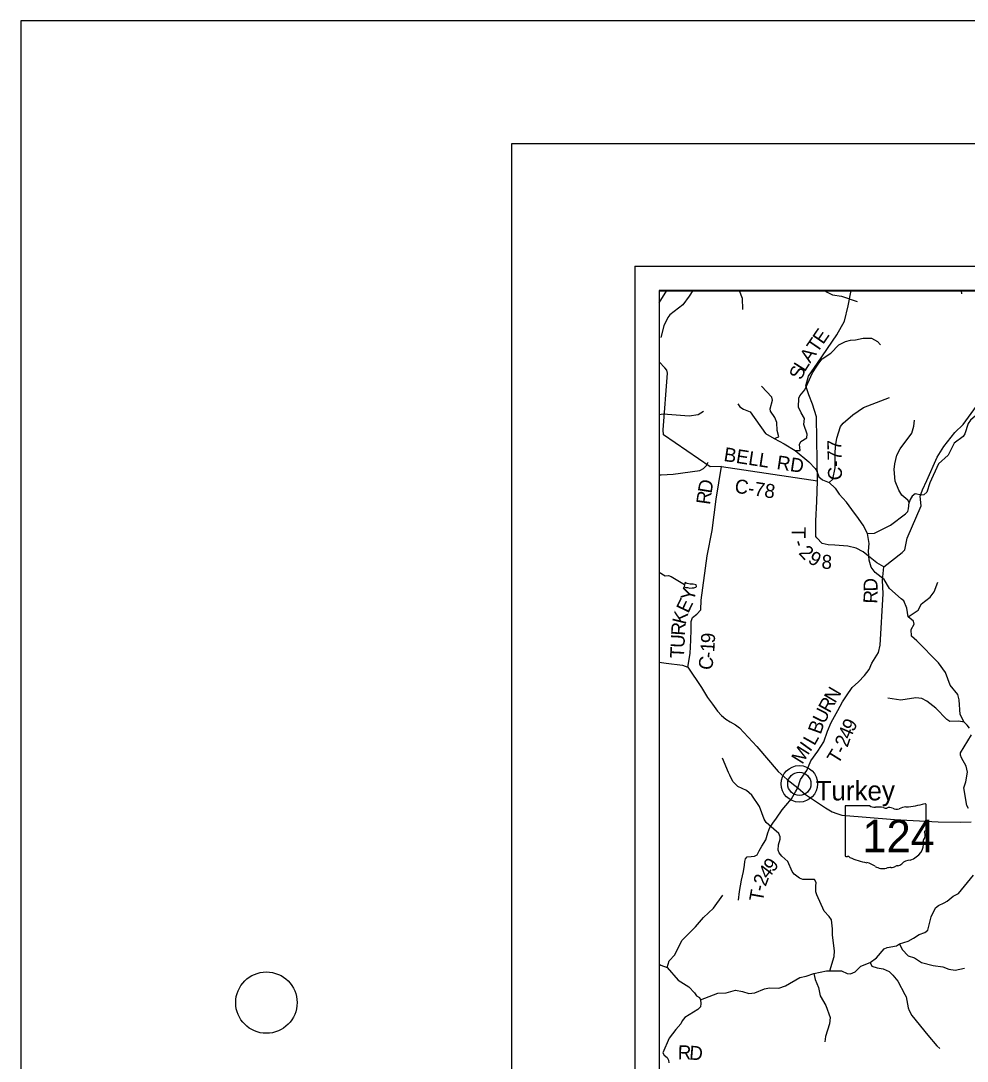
# Model space of a CAD drawing. Extents: x 0 to 34, y 0 to 22.
# Drawn here: x 0 to 3.854, y 17.761 to 22 of the extents above; entities that cross this region are included whole.
import ezdxf

# ---------------------------------------------------------------- set-up
doc = ezdxf.new("R2010")
doc.units = 0
for name, color, linetype in [('GM_X_County', 7, 'Continuous'), ('GM_X_County_Road', 7, 'Continuous'), ('GM_X_County_Road_Text', 7, 'Continuous'), ('GM_X_Minor_Lake', 7, 'Continuous'), ('GM_X_Minor_River', 7, 'Continuous'), ('GM_X_State_Location', 7, 'Continuous'), ('GM_X_State_Route', 7, 'Continuous'), ('GM_X_State_Shield', 7, 'Continuous'), ('GM_X_Township', 7, 'Continuous'), ('GM_X_Township_Road', 7, 'Continuous'), ('GM_X_Township_Road_Text', 7, 'Continuous'), ('GM_X_Unincorporated', 7, 'Continuous'), ('GM_X_Unincorporated_Location', 7, 'Continuous'), ('GM_X_Unincorporated_Text', 7, 'Continuous'), ('SH_Border', 7, 'Continuous'), ('SH_Cut_Line', 7, 'Continuous'), ('SH_Data', 7, 'Continuous')]:
    doc.layers.add(name, color=color, linetype=linetype)

msp = doc.modelspace()

# ---------------------------------------------------------------- linework, layer by layer
at = {"layer": 'GM_X_County'}
msp.add_lwpolyline([(7.6111, 20.9006), (2.6, 20.9006), (2.6, 14.46)], dxfattribs=at)
at = {"layer": 'GM_X_County_Road'}
for points in [[(3.2448, 20.1261), (3.2409, 20.2936), (3.2401, 20.3871), (3.2231, 20.4376), (3.2085, 20.4756), (3.1968, 20.5135), (3.2073, 20.552), (3.2446, 20.6047), (3.3224, 20.7203), (3.3537, 20.7766), (3.3689, 20.8386), (3.3814, 20.9006)], [(2.716, 19.367), (2.7257, 19.423), (2.7284, 19.4769), (2.7293, 19.5198), (2.7294, 19.5521), (2.7358, 19.5696), (2.7528, 19.583), (2.7686, 19.6009), (2.7698, 19.6396), (2.7948, 19.8201), (2.8154, 19.9231), (2.8313, 20.0515), (2.8536, 20.1849), (2.8065, 20.1823), (2.6165, 20.3129), (2.6151, 20.3339), (2.6337, 20.5651), (2.6302, 20.5763), (2.6226, 20.5864), (2.6, 20.611)], [(2.8536, 20.1849), (3.2448, 20.1261)]]:
    msp.add_lwpolyline(points, dxfattribs=at)
at = {"layer": 'GM_X_Minor_Lake'}
for points in [[(2.7029, 19.704), (2.701, 19.6942), (2.7074, 19.6918), (2.7145, 19.6906), (2.724, 19.689), (2.7338, 19.6893), (2.7406, 19.69), (2.7482, 19.6926), (2.7517, 19.696), (2.7498, 19.7017), (2.7381, 19.7044), (2.7257, 19.7049), (2.7136, 19.7077), (2.709, 19.7089), (2.7053, 19.7116)], [(2.7053, 19.7116), (2.7029, 19.704)]]:
    msp.add_lwpolyline(points, dxfattribs=at)
at = {"layer": 'GM_X_Minor_River'}
for points in [[(2.7361, 20.9006), (2.7216, 20.878), (2.6951, 20.8431), (2.6435, 20.8015), (2.6349, 20.7918), (2.6187, 20.7567), (2.606, 20.7095)], [(2.9249, 20.9006), (2.9371, 20.8699), (2.9382, 20.8243)], [(3.2744, 20.9006), (3.2831, 20.8945), (3.3057, 20.8831), (3.3413, 20.8779), (3.405, 20.8558)], [(3.8296, 20.9006), (3.8296, 20.8999), (3.8305, 20.8881)], [(4.0014, 20.7517), (3.9944, 20.7211), (3.9907, 20.6847), (3.9892, 20.5855), (3.9875, 20.5343), (3.9806, 20.5123), (3.9499, 20.4529), (3.9157, 20.4151), (3.8675, 20.373), (3.8581, 20.3595), (3.844, 20.3168), (3.837, 20.3071), (3.8004, 20.2789), (3.7897, 20.257), (3.7756, 20.2307), (3.7366, 20.1957), (3.7009, 20.118), (3.6888, 20.0795), (3.6776, 20.0694), (3.6677, 20.0677), (3.6413, 20.0735), (3.6293, 20.0631), (3.6211, 20.0503), (3.617, 20.0375)], [(3.1529, 20.249), (3.1741, 20.2494), (3.1708, 20.2742), (3.176, 20.2862), (3.2006, 20.3014), (3.202, 20.3154), (3.1887, 20.3555), (3.191, 20.3802), (3.1774, 20.4032), (3.1668, 20.4266), (3.1675, 20.4623), (3.1719, 20.4721), (3.1928, 20.4964), (3.2242, 20.5665), (3.2382, 20.5887), (3.2464, 20.6011), (3.2632, 20.6232), (3.2978, 20.6458), (3.3307, 20.6794), (3.3575, 20.6933), (3.3789, 20.6994), (3.3991, 20.7006), (3.4295, 20.7065), (3.4641, 20.7074), (3.4889, 20.6929), (3.5004, 20.6797)], [(3.0672, 20.2988), (3.0864, 20.3057), (3.08, 20.3313), (3.0783, 20.3632), (3.0707, 20.3842), (3.0534, 20.4096), (3.052, 20.4191), (3.0607, 20.454), (3.0579, 20.4673), (3.0158, 20.511)], [(2.9192, 20.4402), (2.9284, 20.4271), (2.9423, 20.4177), (2.9698, 20.4073), (3.0323, 20.3181), (3.0672, 20.2988), (3.1086, 20.2768), (3.1529, 20.249), (3.2094, 20.2036), (3.2346, 20.1758), (3.2413, 20.1646), (3.2496, 20.1424), (3.2641, 20.1293), (3.292, 20.1189), (3.3167, 20.096), (3.3325, 20.0718), (3.3616, 20.0394)], [(3.292, 20.1189), (3.306, 20.1331), (3.3167, 20.1788), (3.3164, 20.2442), (3.3193, 20.2742), (3.3232, 20.2996), (3.3374, 20.3475), (3.3483, 20.3614), (3.388, 20.3953), (3.4311, 20.4241), (3.537, 20.4648)], [(2.6, 20.3958), (2.6158, 20.3989), (2.7219, 20.3913), (2.7577, 20.3963), (2.7804, 20.41)], [(3.617, 20.0375), (3.6115, 20.0471), (3.5876, 20.0672), (3.5747, 20.0872), (3.5602, 20.1243), (3.5565, 20.1715), (3.5593, 20.1954), (3.5675, 20.2298), (3.5813, 20.2558), (3.6284, 20.3196), (3.6366, 20.3487), (3.6385, 20.3733)], [(2.6, 20.1502), (2.6077, 20.1505), (2.6563, 20.1527), (2.7656, 20.1682), (2.7798, 20.1763), (2.7925, 20.1886), (2.7989, 20.2014)], [(3.8631, 19.1187), (3.8534, 19.1302), (3.8407, 19.1421), (3.8247, 19.1744), (3.8208, 19.234), (3.8153, 19.256), (3.7847, 19.2931), (3.7651, 19.3445), (3.7371, 19.3838), (3.6488, 19.4737), (3.627, 19.4929), (3.6258, 19.5198), (3.6381, 19.5421), (3.6356, 19.5546), (3.6127, 19.5723), (3.6081, 19.6068), (3.5955, 19.6365), (3.5846, 19.6457), (3.537, 19.6867), (3.5154, 19.7245), (3.4783, 19.7525), (3.4626, 19.7746), (3.4542, 19.802), (3.4519, 19.8396), (3.4552, 19.871), (3.4481, 19.9116), (3.4302, 19.9448), (3.4041, 19.9818), (3.3948, 19.9937), (3.3616, 20.0394)], [(3.4481, 19.9116), (3.4761, 19.9129), (3.5418, 19.9456), (3.6025, 19.992), (3.612, 20.001), (3.6148, 20.0112), (3.617, 20.0375)], [(2.6, 19.7541), (2.6242, 19.7393), (2.6375, 19.7407), (2.6488, 19.736), (2.7029, 19.704)], [(3.6127, 19.5723), (3.6538, 19.5992), (3.6673, 19.6252), (3.7035, 19.6521), (3.7188, 19.6743), (3.7347, 19.7128)], [(3.8407, 19.1421), (3.8203, 19.1464), (3.7832, 19.1457), (3.7708, 19.1534), (3.7259, 19.1997), (3.6887, 19.2285), (3.6684, 19.2393), (3.6446, 19.2414), (3.5836, 19.2325), (3.5307, 19.2402)], [(3.8584, 18.7905), (3.8521, 18.8027), (3.8395, 18.8745), (3.8485, 18.9001), (3.8553, 18.9391), (3.8495, 18.9634), (3.8302, 18.9977), (3.8265, 19.0076), (3.827, 19.0179), (3.8712, 19.0906)], [(3.2949, 18.13), (3.3125, 18.1878), (3.3131, 18.2109), (3.3051, 18.2751), (3.3049, 18.3012), (3.3008, 18.338), (3.2918, 18.351), (3.2708, 18.3728), (3.2409, 18.4391), (3.2368, 18.452), (3.2371, 18.4747), (3.2387, 18.4891), (3.2324, 18.5021), (3.184, 18.5018), (3.1715, 18.5072), (3.1486, 18.5238), (3.1408, 18.5341), (3.1238, 18.5744), (3.0994, 18.597), (3.0882, 18.61), (3.0834, 18.6211), (3.0851, 18.643), (3.0918, 18.6661), (3.0919, 18.6756), (3.0863, 18.6889), (3.0357, 18.7345), (3.0264, 18.7475), (3.0168, 18.773), (3.0076, 18.7984), (2.977, 18.8457), (2.9545, 18.8642), (2.9199, 18.8804), (2.9, 18.9011), (2.8874, 18.9262), (2.8818, 18.9373), (2.8571, 18.9959)], [(2.7671, 18.0108), (2.8381, 18.0386), (2.8729, 18.0405), (2.9105, 18.0504), (2.9381, 18.0452), (2.9641, 18.0366), (2.9887, 18.0397), (3.0286, 18.0568), (3.0491, 18.06), (3.0869, 18.0596), (3.1142, 18.0688), (3.1728, 18.1028), (3.1975, 18.1074), (3.2294, 18.1189), (3.2805, 18.129), (3.2949, 18.13), (3.3418, 18.1295), (3.3644, 18.1187), (3.378, 18.1174), (3.3978, 18.1252), (3.4203, 18.1489), (3.4587, 18.1633), (3.485, 18.1831), (3.5152, 18.2192), (3.5274, 18.224), (3.5653, 18.2308), (3.5779, 18.2402), (3.6128, 18.2504), (3.6352, 18.262), (3.6577, 18.2777), (3.6816, 18.2854), (3.6934, 18.2959), (3.7072, 18.3492), (3.7246, 18.3858), (3.7364, 18.3963), (3.7596, 18.4071), (3.7721, 18.413), (3.7966, 18.4344), (3.8186, 18.4448), (3.8788, 18.5196)], [(2.6322, 18.1433), (2.6396, 18.1698), (2.6637, 18.1942), (2.6923, 18.2527), (2.7473, 18.3086), (2.7803, 18.3462), (2.8204, 18.3844), (2.8583, 18.4375)], [(3.5779, 18.2402), (3.589, 18.2162), (3.6137, 18.1905), (3.6397, 18.1827), (3.6671, 18.1631), (3.7151, 18.1509), (3.7547, 18.146), (3.7796, 18.137), (3.8045, 18.1322), (3.8425, 18.1398)], [(2.6, 18.157), (2.6066, 18.153)], [(2.6066, 18.153), (2.6322, 18.1433), (2.6771, 18.0917), (2.7203, 18.064), (2.7439, 18.0403), (2.7517, 18.0277), (2.7638, 18.0211), (2.7671, 18.0108), (2.7696, 17.996), (2.7679, 17.9824), (2.7572, 17.9715), (2.704, 17.9398), (2.6936, 17.9263), (2.6882, 17.9131), (2.6668, 17.8905), (2.6399, 17.8548), (2.614, 17.7959), (2.62, 17.7864), (2.6323, 17.7764), (2.6379, 17.7657), (2.6386, 17.7547)], [(3.4587, 18.1633), (3.4653, 18.148), (3.4876, 18.1414), (3.5122, 18.1381), (3.5359, 18.1265), (3.5512, 18.1123), (3.5707, 18.0875), (3.5996, 18.033), (3.6052, 18.0231), (3.6139, 17.9787), (3.6168, 17.9673), (3.6276, 17.9482), (3.6937, 17.8679), (3.73, 17.824), (3.7427, 17.8136)], [(3.2294, 18.1189), (3.2352, 18.0942), (3.2488, 18.0622), (3.2549, 18.0273), (3.278, 17.9888), (3.2953, 17.9397), (3.2935, 17.9143), (3.2767, 17.8614), (3.2735, 17.8402)]]:
    msp.add_lwpolyline(points, dxfattribs=at)
at = {"layer": 'GM_X_State_Route'}
msp.add_lwpolyline([(2.6, 19.3872), (2.6279, 19.3834), (2.6938, 19.3742), (2.716, 19.367), (2.7722, 19.2838), (2.796, 19.2436), (2.8161, 19.2153), (2.837, 19.1877), (2.8531, 19.1693), (2.8703, 19.1546), (2.8884, 19.1445), (2.9099, 19.1321), (2.9264, 19.1201), (2.9975, 19.0437), (3.0838, 18.9416), (3.1206, 18.9089), (3.1642, 18.8754), (3.1957, 18.8484), (3.2769, 18.7939), (3.304, 18.7776), (3.3232, 18.7702), (3.3436, 18.7642), (3.5575, 18.7465), (3.7355, 18.7371), (3.8268, 18.7356), (3.8692, 18.7363)], dxfattribs=at)
at = {"layer": 'GM_X_State_Shield'}
for p, q in [((3.3564, 18.799), (3.3564, 18.5989)), ((3.4562, 18.8024), (3.3597, 18.8024)), ((3.686, 18.7027), (3.686, 18.8074)), ((3.686, 18.7027), (3.686, 18.7027))]:
    msp.add_line(p, q, dxfattribs=at)
for centre, major_axis, start_param, end_param in [((3.3602, 18.7994), (0.00382, 0), 1.712693, 3.28349), ((3.4792, 18.8257), (0.037, 0), 4.042523, 4.731795), ((3.4915, 18.6901), (0.133, 0), 1.404758, 1.657858), ((3.5216, 18.8005), (0.0107, 0), 3.836095, 5.185415), ((3.5373, 18.7773), (0.0222, 0), 0.950623, 2.079405), ((3.566, 18.8091), (0.0267, 0), 4.081561, 5.145723), ((3.6132, 18.7413), (0.0703, 0), 1.699011, 2.107814), ((3.5686, 19.0753), (0.3495, 0), 4.814394, 5.042369), ((3.6824, 18.8078), (0.00367, 0), 6.141152, 7.989035), ((3.6852, 18.695), (0.00568, 0), 1.883978, 3.671073), ((3.649, 18.6818), (0.0341, 0), 5.934695, 6.695948), ((3.6821, 18.7023), (0.00393, 0), 5.05454, 6.418171), ((3.5882, 18.6456), (0.0874, 0), 5.101752, 6.440018), ((3.6992, 18.6589), (0.0248, 0), 2.387724, 3.262537), ((3.3602, 18.5984), (0.00385, 0), 3.00124, 4.508301), ((3.3608, 18.6189), (0.0294, 0), 4.665946, 4.897461), ((3.3668, 18.5873), (0.0106, 0), 0.519207, 1.627899), ((3.5007, 18.7671), (0.2524, 0), 4.195997, 4.488961), ((3.4254, 18.509), (0.079, 0), 0.823519, 1.323587), ((3.5644, 18.5795), (0.0282, 0), 4.937069, 5.64225), ((3.625, 18.5427), (0.0479, 0), 1.647645, 2.488434), ((3.5108, 18.5863), (0.0501, 0), 4.026481, 4.996735), ((3.5398, 18.5172), (0.0412, 0), 1.495662, 1.94098), ((3.5434, 18.5714), (0.0267, 0), 4.691044, 5.507374), ((3.5676, 18.552), (0.00752, 0), 1.147584, 2.315152)]:
    msp.add_ellipse(centre, major_axis=major_axis, ratio=0.8, start_param=start_param, end_param=end_param, dxfattribs=at)
at = {"layer": 'GM_X_Township'}
msp.add_line((2.6, 20.8508), (2.6307, 20.9006), dxfattribs=at)
msp.add_lwpolyline([(2.6307, 20.9006), (2.6, 20.9006), (2.6, 20.8508)], dxfattribs=at)
at = {"layer": 'GM_X_Township_Road'}
for points in [[(3.5141, 19.7748), (3.589, 19.8343), (3.6004, 19.8443), (3.6087, 19.8917), (3.6657, 20.0244), (3.6626, 20.0636), (3.6716, 20.0892), (3.6899, 20.1268), (3.7309, 20.2223), (3.7585, 20.2661), (3.8035, 20.3228), (3.8369, 20.3559), (3.9027, 20.4452), (3.9656, 20.5516), (3.9773, 20.5817), (3.9747, 20.6308), (3.9688, 20.7188), (3.9658, 20.75), (3.976, 20.7828), (4.0123, 20.8557)], [(3.5141, 19.7748), (3.4855, 19.7917), (3.4524, 19.8192), (3.4303, 19.8366), (3.4017, 19.8519), (3.3672, 19.8593), (3.3152, 19.8636), (3.2879, 19.8657), (3.2625, 19.8704), (3.2421, 19.8933), (3.2372, 19.8995), (3.238, 19.9629), (3.2413, 20.0419), (3.2448, 20.1261)], [(3.1642, 18.8754), (3.1753, 18.9084), (3.2001, 18.9457), (3.2166, 18.9853), (3.2459, 19.0242), (3.2699, 19.0619), (3.2844, 19.1053), (3.2997, 19.1411), (3.3267, 19.1906), (3.3466, 19.2256), (3.3616, 19.25), (3.3853, 19.2836), (3.4113, 19.3076), (3.4362, 19.3332), (3.455, 19.3573), (3.465, 19.3831), (3.4785, 19.4045), (3.4924, 19.4258), (3.4998, 19.457), (3.5121, 19.6655), (3.5095, 19.7205), (3.5141, 19.7748)], [(2.9225, 18.4179), (2.9268, 18.4532), (2.9353, 18.4992), (2.943, 18.5349), (2.947, 18.56), (2.9488, 18.5744), (2.9503, 18.5862), (2.9582, 18.5946), (2.9737, 18.5958), (2.9881, 18.5963), (2.9979, 18.6028), (3.0062, 18.618), (3.0174, 18.6371), (3.0332, 18.6638), (3.0417, 18.6912), (3.0503, 18.7132), (3.0623, 18.7308), (3.0766, 18.7521), (3.1007, 18.786), (3.1153, 18.8025), (3.1387, 18.8307), (3.154, 18.8585), (3.1642, 18.8754)]]:
    msp.add_lwpolyline(points, dxfattribs=at)
at = {"layer": 'GM_X_Unincorporated'}
for radius in [0.0744, 0.0472]:
    msp.add_circle((3.1702, 18.8914), radius, dxfattribs=at)
at = {"layer": 'GM_X_Unincorporated_Location'}
msp.add_line((3.1702, 18.8914), (3.1702, 18.8914), dxfattribs=at)
at = {"layer": 'SH_Border'}
msp.add_lwpolyline([(2, 21.5), (33.5, 21.5), (33.5, 0.5), (2, 0.5)], close=True, dxfattribs=at)
msp.add_circle((1, 18), 0.125, dxfattribs=at)
at = {"layer": 'SH_Cut_Line'}
msp.add_lwpolyline([(0, 0), (34, 0), (34, 22), (0, 22)], close=True, dxfattribs=at)
at = {"layer": 'SH_Data'}
for p, q in [((2.5, 21), (9.5, 21)), ((2.5, 21), (2.5, 14)), ((2.6, 20.9), (2.6, 14.1)), ((2.6, 20.9), (9.4, 20.9))]:
    msp.add_line(p, q, dxfattribs=at)

# ---------------------------------------------------------------- texts
at = {"layer": 'GM_X_County_Road_Text'}
for s, height, rotation, p in [('E', 0.0568, 55.531, (3.2667, 20.6787)), ('T', 0.0568, 55.529, (3.2427, 20.6436)), ('A', 0.0568, 55.5532, (3.2144, 20.6024)), ('L', 0.0568, 57.6544, (3.192, 20.5669)), ('S', 0.0568, 68.6353, (3.1793, 20.5338)), ('BELL', 0.05682, 351.1709, (2.8598, 20.2071)), ('C-77', 0.05682, 91.3713, (3.3443, 20.1289)), ('RD', 0.05682, 351.5902, (3.0755, 20.1738)), ('D', 0.0568, 80.4185, (2.8124, 20.0723)), ('C-78', 0.05682, 351.3837, (2.9042, 20.0781)), ('R', 0.0568, 81.898, (2.8059, 20.0265)), ('Y', 0.0568, 75.2793, (2.7401, 19.6328)), ('E', 0.0568, 64.3281, (2.7177, 19.5836)), ('K', 0.0568, 76.1546, (2.7068, 19.538)), ('R', 0.0568, 86.7784, (2.7045, 19.4941)), ('9', 0.0568, 87.6153, (2.826, 19.4633)), ('U', 0.0568, 87.1683, (2.7021, 19.4443)), ('1', 0.0568, 86.3986, (2.8237, 19.4271)), ('T', 0.0568, 87.1703, (2.7, 19.4018)), ('-', 0.0568, 84.6365, (2.8214, 19.4019)), ('C', 0.0568, 81.3058, (2.8139, 19.3522)), ('R', 0.0568, 358.4034, (2.6746, 17.7697)), ('D', 0.0568, 355.5147, (2.7204, 17.7685))]:
    msp.add_text(s, height=height, rotation=rotation, dxfattribs=at).set_placement(p)
at = {"layer": 'GM_X_State_Location'}
msp.add_text('124', height=0.000189, rotation=0, dxfattribs=at).set_placement((3.4507, 18.6719))
for s in ['s', 'r']:
    msp.add_text(s, height=0.000189, dxfattribs=at).set_placement((3.5175, 18.6856))
at = {"layer": 'GM_X_State_Shield'}
msp.add_text('124', height=0.13184, dxfattribs=at).set_placement((3.4275, 18.613))
at = {"layer": 'GM_X_Township_Road_Text'}
for s, rotation, p in [('T', 269.3786, (3.1396, 19.9386)), ('-', 288.7107, (3.1424, 19.8756)), ('2', 314.4888, (3.1643, 19.8299)), ('9', 329.062, (3.2012, 19.7953)), ('8', 356.6817, (3.2595, 19.7685)), ('D', 91.7744, (3.4894, 19.6758)), ('R', 87.7279, (3.4875, 19.6248)), ('N', 59.4698, (3.3162, 19.2171)), ('U', 63.5539, (3.272, 19.1323)), ('R', 61.2282, (3.294, 19.1766)), ('B', 70.0012, (3.2567, 19.09)), ('4', 66.6203, (3.3771, 19.0694)), ('9', 62.3946, (3.3905, 19.1006)), ('L', 60.4706, (3.2315, 19.0439)), ('2', 70.7618, (3.366, 19.0374)), ('M', 57.9714, (3.182, 18.9678)), ('I', 54.0794, (3.2142, 19.0192)), ('T', 58.2013, (3.3274, 18.9681)), ('-', 63.6953, (3.3527, 19.0094)), ('9', 54.4136, (3.0654, 18.5289)), ('2', 69.6047, (3.033, 18.4707)), ('4', 52.6919, (3.043, 18.4996)), ('T', 79.8021, (3.0211, 18.4086)), ('-', 77.5296, (3.0285, 18.4499))]:
    msp.add_text(s, height=0.0568, rotation=rotation, dxfattribs=at).set_placement(p)
at = {"layer": 'GM_X_Unincorporated_Text'}
msp.add_text('Turkey', height=0.07898, rotation=0, dxfattribs=at).set_placement((3.2365, 18.824))

doc.saveas('drawing.dxf')
